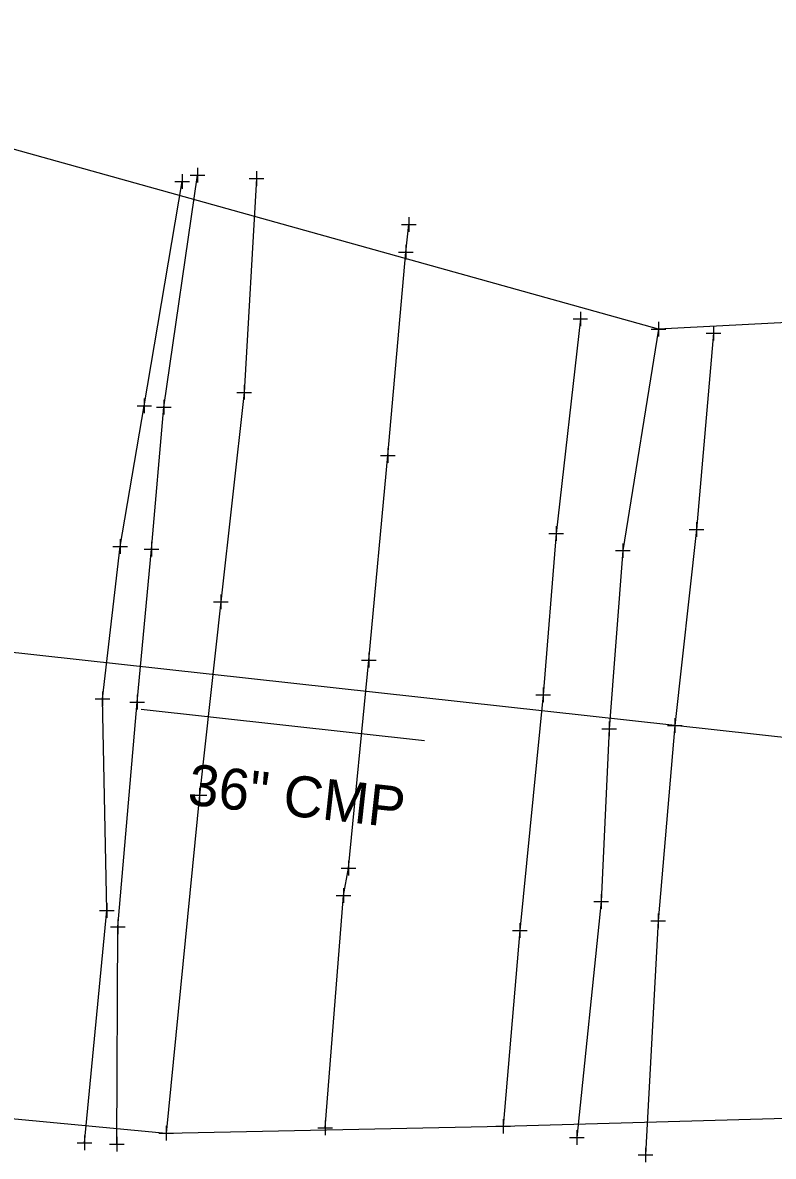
# Model space of a CAD drawing. Extents: x 160138 to 160780, y 488720 to 491073.
# Drawn here: x 160674.2 to 160725.5, y 489676.8 to 489754.3 of the extents above; entities that cross this region are included whole.
import ezdxf

# ---------------------------------------------------------------- set-up
doc = ezdxf.new("R2010")
doc.units = 0
for name, color, linetype in [('DR_X_Storm_Sewer', 7, 'Continuous'), ('DR_X_Text', 7, 'Continuous'), ('GE_X_Alignment_500_Bearings', 7, 'Continuous'), ('GE_X_Alignment_500_Cardinal_Points', 7, 'Continuous'), ('GE_X_Alignment_500_Stations', 7, 'Continuous'), ('PM_X_CL_Double_Solid', 7, 'Continuous'), ('RW_X_CL_100_Distances', 7, 'Continuous'), ('SV_P_Control_Cells_Set', 7, 'Continuous'), ('SV_X_Random_Point', 7, 'Continuous'), ('SV_X_Terrain_Boundary', 7, 'Continuous')]:
    doc.layers.add(name, color=color, linetype=linetype)

msp = doc.modelspace()

# ---------------------------------------------------------------- linework, layer by layer
at = {"layer": 'DR_X_Storm_Sewer'}
msp.add_line((160736.136, 489704.301), (160652.451, 489713.545), dxfattribs=at)
at = {"layer": 'DR_X_Text'}
msp.add_line((160682.311, 489707.329), (160701.663, 489705.192), dxfattribs=at)
at = {"layer": 'GE_X_Alignment_500_Bearings'}
for points in [[(160690.186, 489743.6), (160689.341, 489728.99), (160687.739, 489714.676), (160686.285, 489701.462), (160684.014, 489678.351)], [(160712.307, 489734.003), (160710.661, 489719.345), (160709.771, 489708.316), (160708.177, 489692.217), (160707.031, 489678.823)]]:
    msp.add_lwpolyline(points, dxfattribs=at)
at = {"layer": 'GE_X_Alignment_500_Cardinal_Points'}
msp.add_lwpolyline([(160696.129, 489694.597), (160696.459, 489696.474), (160697.853, 489710.687), (160699.157, 489724.677), (160700.379, 489738.575), (160700.59, 489740.461)], dxfattribs=at)
at = {"layer": 'GE_X_Alignment_500_Stations'}
msp.add_lwpolyline([(160678.439, 489677.705), (160679.955, 489693.577), (160679.666, 489708.041), (160680.87, 489718.459), (160682.518, 489728.059), (160685.102, 489743.396)], dxfattribs=at)
at = {"layer": 'PM_X_CL_Double_Solid'}
msp.add_lwpolyline([(160694.878, 489678.724), (160696.129, 489694.597), (160696.459, 489696.474), (160697.853, 489710.687), (160699.157, 489724.677), (160700.379, 489738.575), (160700.59, 489740.461)], dxfattribs=at)
at = {"layer": 'RW_X_CL_100_Distances'}
for points in [[(160680.65, 489677.612), (160680.707, 489692.45), (160682.035, 489707.823), (160683.016, 489718.277), (160683.853, 489727.982), (160686.152, 489743.824)], [(160717.641, 489733.306), (160715.214, 489718.169), (160714.268, 489706), (160713.724, 489694.18), (160712.077, 489678.055)]]:
    msp.add_lwpolyline(points, dxfattribs=at)
at = {"layer": 'SV_P_Control_Cells_Set'}
msp.add_lwpolyline([(160721.405, 489733.024), (160720.235, 489719.61), (160718.768, 489706.221), (160717.63, 489692.87), (160716.754, 489676.864)], dxfattribs=at)
at = {"layer": 'SV_X_Random_Point'}
for p, q in [((160686.152, 489744.324), (160686.152, 489743.324)), ((160690.186, 489744.1), (160690.186, 489743.1)), ((160684.602, 489743.396), (160685.602, 489743.396)), ((160685.102, 489743.896), (160685.102, 489742.896)), ((160685.102, 489743.396), (160685.102, 489743.396)), ((160685.652, 489743.824), (160686.652, 489743.824)), ((160686.152, 489743.824), (160686.152, 489743.824)), ((160689.686, 489743.6), (160690.686, 489743.6)), ((160690.186, 489743.6), (160690.186, 489743.6)), ((160700.59, 489740.961), (160700.59, 489739.961)), ((160700.59, 489740.961), (160700.59, 489739.961)), ((160700.09, 489740.461), (160701.09, 489740.461)), ((160700.09, 489740.461), (160701.09, 489740.461)), ((160700.59, 489740.461), (160700.59, 489740.461)), ((160700.59, 489740.461), (160700.59, 489740.461)), ((160700.379, 489739.075), (160700.379, 489738.075)), ((160700.379, 489739.075), (160700.379, 489738.075)), ((160699.879, 489738.575), (160700.879, 489738.575)), ((160699.879, 489738.575), (160700.879, 489738.575)), ((160700.379, 489738.575), (160700.379, 489738.575)), ((160700.379, 489738.575), (160700.379, 489738.575)), ((160711.807, 489734.003), (160712.807, 489734.003)), ((160712.307, 489734.503), (160712.307, 489733.503)), ((160712.307, 489734.003), (160712.307, 489734.003)), ((160717.141, 489733.306), (160718.141, 489733.306)), ((160717.641, 489733.806), (160717.641, 489732.806)), ((160717.641, 489733.306), (160717.641, 489733.306)), ((160721.405, 489733.524), (160721.405, 489732.524)), ((160720.905, 489733.024), (160721.905, 489733.024)), ((160721.405, 489733.024), (160721.405, 489733.024)), ((160689.341, 489729.49), (160689.341, 489728.49)), ((160682.518, 489728.559), (160682.518, 489727.559)), ((160688.841, 489728.99), (160689.841, 489728.99)), ((160689.341, 489728.99), (160689.341, 489728.99)), ((160682.018, 489728.059), (160683.018, 489728.059)), ((160682.518, 489728.059), (160682.518, 489728.059)), ((160683.353, 489727.982), (160684.353, 489727.982)), ((160683.853, 489728.482), (160683.853, 489727.482)), ((160683.853, 489727.982), (160683.853, 489727.982)), ((160698.657, 489724.677), (160699.657, 489724.677)), ((160698.657, 489724.677), (160699.657, 489724.677)), ((160699.157, 489725.177), (160699.157, 489724.177)), ((160699.157, 489725.177), (160699.157, 489724.177)), ((160699.157, 489724.677), (160699.157, 489724.677)), ((160699.157, 489724.677), (160699.157, 489724.677)), ((160720.235, 489720.11), (160720.235, 489719.11)), ((160710.161, 489719.345), (160711.161, 489719.345)), ((160710.661, 489719.845), (160710.661, 489718.845)), ((160710.661, 489719.345), (160710.661, 489719.345)), ((160719.735, 489719.61), (160720.735, 489719.61)), ((160720.235, 489719.61), (160720.235, 489719.61)), ((160680.37, 489718.459), (160681.37, 489718.459)), ((160680.87, 489718.959), (160680.87, 489717.959)), ((160680.87, 489718.459), (160680.87, 489718.459)), ((160683.016, 489718.777), (160683.016, 489717.777)), ((160715.214, 489718.669), (160715.214, 489717.669)), ((160682.516, 489718.277), (160683.516, 489718.277)), ((160683.016, 489718.277), (160683.016, 489718.277)), ((160714.714, 489718.169), (160715.714, 489718.169)), ((160715.214, 489718.169), (160715.214, 489718.169)), ((160687.239, 489714.676), (160688.239, 489714.676)), ((160687.739, 489715.176), (160687.739, 489714.176)), ((160687.739, 489714.676), (160687.739, 489714.676)), ((160697.353, 489710.687), (160698.353, 489710.687)), ((160697.353, 489710.687), (160698.353, 489710.687)), ((160697.853, 489711.187), (160697.853, 489710.187)), ((160697.853, 489711.187), (160697.853, 489710.187)), ((160697.853, 489710.687), (160697.853, 489710.687)), ((160697.853, 489710.687), (160697.853, 489710.687)), ((160679.666, 489708.541), (160679.666, 489707.541)), ((160709.771, 489708.816), (160709.771, 489707.816)), ((160679.166, 489708.041), (160680.166, 489708.041)), ((160679.666, 489708.041), (160679.666, 489708.041)), ((160681.535, 489707.823), (160682.535, 489707.823)), ((160682.035, 489708.323), (160682.035, 489707.323)), ((160682.035, 489707.823), (160682.035, 489707.823)), ((160709.271, 489708.316), (160710.271, 489708.316)), ((160709.771, 489708.316), (160709.771, 489708.316)), ((160714.268, 489706.5), (160714.268, 489705.5)), ((160718.268, 489706.221), (160719.268, 489706.221)), ((160718.768, 489706.721), (160718.768, 489705.721)), ((160718.768, 489706.221), (160718.768, 489706.221)), ((160713.768, 489706), (160714.768, 489706)), ((160714.268, 489706), (160714.268, 489706)), ((160685.785, 489701.462), (160686.785, 489701.462)), ((160686.285, 489701.962), (160686.285, 489700.962)), ((160686.285, 489701.462), (160686.285, 489701.462)), ((160696.459, 489696.974), (160696.459, 489695.974)), ((160696.459, 489696.974), (160696.459, 489695.974)), ((160695.959, 489696.474), (160696.959, 489696.474)), ((160695.959, 489696.474), (160696.959, 489696.474)), ((160696.459, 489696.474), (160696.459, 489696.474)), ((160696.459, 489696.474), (160696.459, 489696.474)), ((160695.629, 489694.597), (160696.629, 489694.597)), ((160695.629, 489694.597), (160696.629, 489694.597)), ((160696.129, 489695.097), (160696.129, 489694.097)), ((160696.129, 489695.097), (160696.129, 489694.097)), ((160696.129, 489694.597), (160696.129, 489694.597)), ((160696.129, 489694.597), (160696.129, 489694.597)), ((160713.724, 489694.68), (160713.724, 489693.68)), ((160679.955, 489694.077), (160679.955, 489693.077)), ((160713.224, 489694.18), (160714.224, 489694.18)), ((160713.724, 489694.18), (160713.724, 489694.18)), ((160679.455, 489693.577), (160680.455, 489693.577)), ((160679.955, 489693.577), (160679.955, 489693.577)), ((160680.707, 489692.95), (160680.707, 489691.95)), ((160717.13, 489692.87), (160718.13, 489692.87)), ((160717.63, 489693.37), (160717.63, 489692.37)), ((160717.63, 489692.87), (160717.63, 489692.87)), ((160680.207, 489692.45), (160681.207, 489692.45)), ((160680.707, 489692.45), (160680.707, 489692.45)), ((160707.677, 489692.217), (160708.677, 489692.217)), ((160708.177, 489692.717), (160708.177, 489691.717)), ((160708.177, 489692.217), (160708.177, 489692.217)), ((160694.878, 489679.224), (160694.878, 489678.224)), ((160694.878, 489679.224), (160694.878, 489678.224)), ((160707.031, 489679.323), (160707.031, 489678.323)), ((160678.439, 489678.205), (160678.439, 489677.205)), ((160683.514, 489678.351), (160684.514, 489678.351)), ((160684.014, 489678.851), (160684.014, 489677.851)), ((160684.014, 489678.351), (160684.014, 489678.351)), ((160694.378, 489678.724), (160695.378, 489678.724)), ((160694.378, 489678.724), (160695.378, 489678.724)), ((160694.878, 489678.724), (160694.878, 489678.724)), ((160694.878, 489678.724), (160694.878, 489678.724)), ((160706.531, 489678.823), (160707.531, 489678.823)), ((160707.031, 489678.823), (160707.031, 489678.823)), ((160712.077, 489678.555), (160712.077, 489677.555)), ((160677.939, 489677.705), (160678.939, 489677.705)), ((160678.439, 489677.705), (160678.439, 489677.705)), ((160680.15, 489677.612), (160681.15, 489677.612)), ((160680.65, 489678.112), (160680.65, 489677.112)), ((160680.65, 489677.612), (160680.65, 489677.612)), ((160711.577, 489678.055), (160712.577, 489678.055)), ((160712.077, 489678.055), (160712.077, 489678.055)), ((160716.254, 489676.864), (160717.254, 489676.864)), ((160716.754, 489677.364), (160716.754, 489676.364)), ((160716.754, 489676.864), (160716.754, 489676.864))]:
    msp.add_line(p, q, dxfattribs=at)
at = {"layer": 'SV_X_Terrain_Boundary'}
msp.add_lwpolyline([(160514.912, 489637.894), (160547.865, 489638.238), (160565.434, 489639.08), (160616.189, 489674.183), (160652.272, 489681.356), (160684.014, 489678.351), (160707.031, 489678.823), (160736.83, 489679.671), (160750.025, 489679.19), (160759.846, 489681.649), (160765.268, 489684.51), (160772.898, 489693.362), (160771.249, 489707.538), (160769.281, 489717.032), (160767.493, 489724.397), (160754.691, 489734.763), (160746.199, 489734.784), (160717.641, 489733.306), (160642.598, 489754.256), (160573.958, 489735.815), (160560.406, 489729.318), (160491.054, 489700.611)], dxfattribs=at)

# ---------------------------------------------------------------- texts
at = {"layer": 'DR_X_Text'}
msp.add_text('36" CMP', height=2.8, rotation=353.69651, dxfattribs=at).set_placement((160685.407, 489700.824))

doc.saveas('drawing.dxf')
